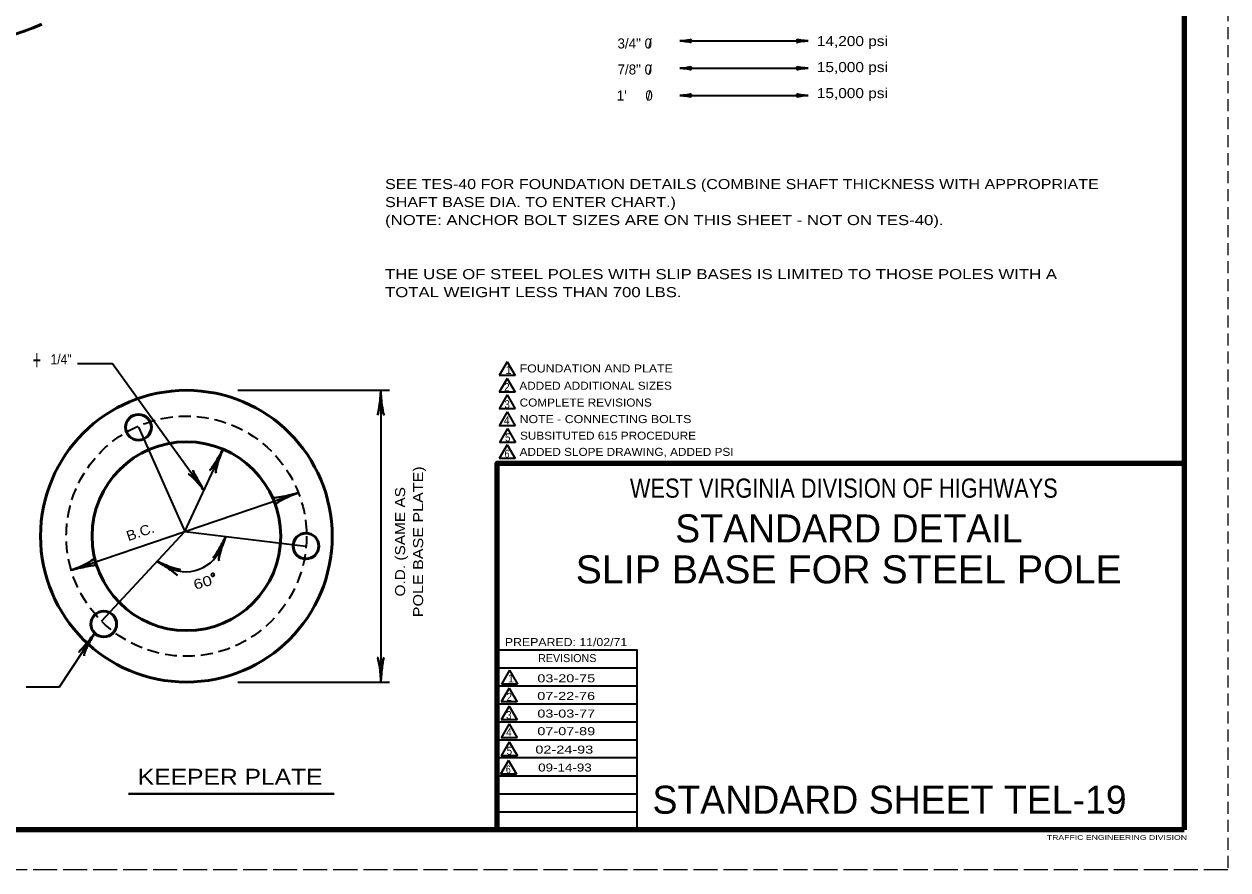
# Model space of a CAD drawing. Extents: x -2 to 678, y 0 to 440.
# Drawn here: x 377.6 to 678.4, y -0.1 to 211.2 of the extents above; entities that cross this region are included whole.
import ezdxf
from ezdxf.enums import TextEntityAlignment as Align

# ---------------------------------------------------------------- set-up
doc = ezdxf.new("R2010")
doc.units = 0
doc.linetypes.add('LONG_DASHED', pattern=[7.5, 6, -1.5])
doc.linetypes.add('MEDIUM_DASHED', pattern=[4.5, 3, -1.5])
doc.layers.add('1', color=7, linetype='Continuous', lineweight=53)
doc.layers.add('61', color=7, linetype='Continuous', lineweight=35)

msp = doc.modelspace()

# ---------------------------------------------------------------- linework, layer by layer
at = {"layer": '1', "linetype": 'MEDIUM_DASHED', "lineweight": 13}
msp.add_line((678.423, 439.973), (678.403, -0.047), dxfattribs=at)
at = {"layer": '1', "lineweight": 35}
for p, q in [((541.511, 207.033), (573.511, 207.033)), ((541.511, 200.213), (573.511, 200.213)), ((541.511, 193.392), (573.511, 193.392)), ((498.341, 126.882), (496.341, 123.418)), ((498.341, 126.882), (500.341, 123.418)), ((500.341, 123.418), (496.341, 123.418)), ((498.326, 122.716), (496.326, 119.252)), ((498.326, 122.716), (500.326, 119.252)), ((431.057, 119.74), (468.914, 119.74)), ((466.77, 119.74), (466.77, 46.858)), ((500.326, 119.252), (496.326, 119.252)), ((498.361, 118.585), (496.361, 115.121)), ((498.361, 118.585), (500.361, 115.121)), ((500.361, 115.121), (496.361, 115.121)), ((498.361, 114.341), (496.361, 110.877)), ((498.361, 114.341), (500.361, 110.877)), ((500.361, 110.877), (496.361, 110.877)), ((498.444, 110.203), (496.444, 106.739)), ((498.444, 110.203), (500.444, 106.739)), ((498.356, 106.151), (496.356, 102.686)), ((500.444, 106.739), (496.444, 106.739)), ((498.356, 106.151), (500.356, 102.686)), ((417.796, 84.471), (427.351, 105.028)), ((500.356, 102.686), (496.356, 102.686)), ((389.417, 74.79), (446.175, 94.153)), ((396.975, 62.078), (417.796, 84.471)), ((530.803, 50.373), (495.823, 50.373)), ((498.882, 49.832), (496.882, 46.368)), ((498.882, 49.832), (500.882, 46.368)), ((431.057, 46.858), (468.914, 46.858)), ((530.803, 45.873), (495.823, 45.873)), ((498.827, 45.377), (496.827, 41.913)), ((500.882, 46.368), (496.882, 46.368)), ((498.827, 45.377), (500.827, 41.913)), ((530.803, 41.373), (495.823, 41.373)), ((500.827, 41.913), (496.827, 41.913)), ((498.839, 40.879), (496.839, 37.415)), ((498.839, 40.879), (500.839, 37.415)), ((530.803, 36.853), (495.823, 36.853)), ((500.839, 37.415), (496.839, 37.415)), ((498.847, 36.401), (496.847, 32.937)), ((498.847, 36.401), (500.847, 32.937)), ((530.803, 32.373), (495.823, 32.373)), ((500.847, 32.937), (496.847, 32.937)), ((498.88, 31.915), (496.88, 28.45)), ((498.88, 31.915), (500.88, 28.45)), ((530.803, 27.893), (495.823, 27.893)), ((498.686, 27.303), (496.686, 23.839)), ((500.88, 28.45), (496.88, 28.45)), ((498.686, 27.303), (500.686, 23.839)), ((530.803, 23.393), (495.823, 23.393)), ((500.686, 23.839), (496.686, 23.839)), ((530.803, 18.893), (495.823, 18.893)), ((530.803, 14.373), (495.823, 14.373))]:
    msp.add_line(p, q, dxfattribs=at)
at = {"layer": '1', "lineweight": 40}
msp.add_line((403.734, 18.941), (455.095, 18.941), dxfattribs=at)
at = {"layer": '1', "lineweight": 35}
for points in [[(422.573, 94.75), (399.746, 126.363), (390.973, 126.363)], [(406.218, 110.509), (417.796, 84.471), (448.062, 80.845)], [(395.279, 59.083), (386.426, 45.554), (378.139, 45.554)], [(530.803, 9.893), (530.803, 54.853), (495.823, 54.853)]]:
    msp.add_lwpolyline(points, dxfattribs=at)
at = {"layer": '1', "lineweight": 158}
msp.add_lwpolyline([(495.803, 9.933), (495.803, 101.513), (667.463, 101.513)], dxfattribs=at)
at = {"layer": '1'}
for centre, radius in [((418.196, 83.299), 36.441), ((406.218, 110.509), 3.215), ((418.196, 83.299), 23.579), ((448.062, 80.845), 3.215), ((397.552, 61.357), 3.215)]:
    msp.add_circle(centre, radius, dxfattribs=at)
at = {"layer": '1', "linetype": 'MEDIUM_DASHED', "lineweight": 35}
msp.add_circle((418.196, 83.299), 30.01, dxfattribs=at)
at = {"layer": '1', "lineweight": 35}
msp.add_circle((424.796, 73.648), 0.394, dxfattribs=at)
at = {"layer": '1'}
msp.add_arc((363.469, 250.283), 43.26, 245.44681, 295.48154, dxfattribs=at)
at = {"layer": '1', "lineweight": 35}
msp.add_arc((418.077, 83.89), 9.464, 237.85816, 343.17714, dxfattribs=at)
at = {"layer": '1', "lineweight": 40}
for centre, major_axis, ratio, start_param, end_param in [((542.631, 206.821), (1.756, -0.176), 0.07063, 6.2823074, 8.5597026), ((542.631, 206.821), (1.756, -0.176), 0.07063, 6.2823074, 8.5597026), ((542.602, 207.309), (-1.786, -0.156), 0.122415, 0.8963533, 3.1415927), ((542.602, 207.309), (-1.786, -0.156), 0.122415, 0.8963533, 3.1415927), ((572.42, 206.757), (1.786, 0.156), 0.122415, 0.8963533, 3.1415927), ((572.42, 206.757), (1.786, 0.156), 0.122415, 0.8963533, 3.1415927), ((572.39, 207.245), (-1.756, 0.176), 0.07063, 6.2823074, 8.5597026), ((572.39, 207.245), (-1.756, 0.176), 0.07063, 6.2823074, 8.5597026), ((542.631, 200.001), (1.756, -0.176), 0.07063, 6.2823074, 8.5597026), ((542.631, 200.001), (1.756, -0.176), 0.07063, 6.2823074, 8.5597026), ((542.602, 200.489), (-1.786, -0.156), 0.122415, 0.8963533, 3.1415927), ((542.602, 200.489), (-1.786, -0.156), 0.122415, 0.8963533, 3.1415927), ((572.42, 199.936), (1.786, 0.156), 0.122415, 0.8963533, 3.1415927), ((572.42, 199.936), (1.786, 0.156), 0.122415, 0.8963533, 3.1415927), ((572.39, 200.424), (-1.756, 0.176), 0.07063, 6.2823074, 8.5597026), ((572.39, 200.424), (-1.756, 0.176), 0.07063, 6.2823074, 8.5597026), ((542.631, 193.181), (1.756, -0.176), 0.07063, 6.2823074, 8.5597026), ((542.602, 193.669), (-1.786, -0.156), 0.122415, 0.8963533, 3.1415927), ((572.42, 193.116), (1.786, 0.156), 0.122415, 0.8963533, 3.1415927), ((572.42, 193.116), (1.786, 0.156), 0.122415, 0.8963533, 3.1415927), ((572.39, 193.604), (-1.756, 0.176), 0.07063, 6.2823074, 8.5597026), ((572.39, 193.604), (-1.756, 0.176), 0.07063, 6.2823074, 8.5597026), ((466.316, 117.338), (0.377, 3.765), 0.07063, 3.1407148, 5.41811), ((466.316, 117.338), (0.377, 3.765), 0.07063, 3.1407148, 5.41811), ((467.362, 117.401), (-0.335, 3.828), 0.122415, 0.8963533, 3.1415927), ((467.362, 117.401), (-0.335, 3.828), 0.122415, 0.8963533, 3.1415927), ((425.927, 103.041), (1.928, 3.256), 0.07063, 3.1407148, 5.41811), ((426.902, 102.657), (1.31, 3.612), 0.122415, 0.8963533, 3.1415927), ((421.632, 96.785), (1.726, -2.975), 0.07063, 3.1407148, 5.41811), ((420.894, 96.182), (2.284, -2.643), 0.122415, 0.8963533, 3.1415927), ((443.755, 93.806), (3.685, 0.859), 0.07063, 3.1407148, 5.41811), ((443.755, 93.806), (3.685, 0.859), 0.07063, 3.1407148, 5.41811), ((444.152, 92.837), (3.515, 1.553), 0.122415, 0.8963533, 3.1415927), ((444.152, 92.837), (3.515, 1.553), 0.122415, 0.8963533, 3.1415927), ((426.671, 81.169), (1.898, 3.273), 0.07063, 3.1407148, 5.41811), ((427.65, 80.794), (1.277, 3.624), 0.122415, 0.8963533, 3.1415927), ((391.439, 76.106), (-3.515, -1.553), 0.122415, 0.8963533, 3.1415927), ((391.439, 76.106), (-3.515, -1.553), 0.122415, 0.8963533, 3.1415927), ((391.837, 75.136), (-3.685, -0.859), 0.07063, 3.1407148, 5.41811), ((391.837, 75.136), (-3.685, -0.859), 0.07063, 3.1407148, 5.41811), ((412.762, 75.552), (-3.168, 2.07), 0.07063, 3.1407148, 5.41811), ((413.188, 76.51), (-3.551, 1.467), 0.122415, 0.8963533, 3.1415927), ((393.584, 57.322), (2.377, 2.944), 0.07063, 3.1407148, 5.41811), ((394.493, 56.801), (1.816, 3.386), 0.122415, 0.8963533, 3.1415927), ((466.178, 49.197), (0.335, -3.828), 0.122415, 0.8963533, 3.1415927), ((467.224, 49.259), (-0.377, -3.765), 0.07063, 3.1407148, 5.41811)]:
    msp.add_ellipse(centre, major_axis=major_axis, ratio=ratio, start_param=start_param, end_param=end_param, dxfattribs=at)
at = {"layer": '61', "lineweight": 158}
for p, q in [((667.443, 429.973), (667.463, 9.933)), ((667.463, 9.933), (28.403, 9.953))]:
    msp.add_line(p, q, dxfattribs=at)
at = {"layer": '61', "linetype": 'LONG_DASHED', "lineweight": 13}
msp.add_line((678.403, -0.047), (-1.657, -0.067), dxfattribs=at)

# ---------------------------------------------------------------- texts
at = {"layer": '1'}
for s, height, p in [('3/4" 0', 2.5, (530.222, 205.139)), ('7/8" 0', 2.5, (530.222, 198.639)), ("1'     0", 2.5, (530.222, 192.139)), ('STANDARD DETAIL', 6.993, (583.72, 81.753))]:
    msp.add_text(s, height=height, dxfattribs=at).set_placement(p, align=Align.CENTER)
for s, height, p in [('/', 2.5, (533.541, 205.152)), ('/', 2.5, (533.592, 198.576)), ('/', 2.5, (533.287, 192.152)), ('1', 2, (497.947, 123.823)), ('REVISIONS', 1.998, (506.083, 51.853)), ('1', 2, (498.53, 46.77)), ('STANDARD SHEET TEL-19', 6.993, (534.643, 13.973))]:
    msp.add_text(s, height=height, dxfattribs=at).set_placement(p)
for s, height, width, p in [('14,200 psi', 2.5, 1.15, (584.594, 205.741)), ('15,000 psi', 2.5, 1.15, (584.594, 199.241)), ('15,000 psi', 2.5, 1.15, (584.594, 192.741)), ('WEST VIRGINIA DIVISION OF HIGHWAYS', 4.795, 0.85, (582.452, 92.913)), ('SLIP BASE FOR STEEL POLE', 6.993, 1.05, (583.674, 71.516)), ('03-20-75', 2, 1.35, (513.103, 46.793)), ('07-22-76', 2, 1.35, (513.083, 42.393)), ('03-03-77', 2, 1.35, (513.103, 37.993)), ('07-07-89', 2, 1.35, (513.103, 33.593)), ('02-24-93', 2, 1.35, (512.613, 28.993)), ('KEEPER PLATE', 4, 1.15, (429.129, 21.194)), ('09-14-93', 2, 1.25, (512.773, 24.513))]:
    msp.add_text(s, height=height, dxfattribs=dict(at, width=width)).set_placement(p, align=Align.CENTER)
for s, height, width, p in [('SEE TES-40 FOR FOUNDATION DETAILS (COMBINE SHAFT THICKNESS WITH APPROPRIATE', 2.5, 1.2, (467.833, 170.013)), ('SHAFT BASE DIA. TO ENTER CHART.)', 2.5, 1.2, (467.833, 165.513)), ('(NOTE: ANCHOR BOLT SIZES ARE ON THIS SHEET - NOT ON TES-40).', 2.5, 1.25, (467.833, 161.013)), ('THE USE OF STEEL POLES WITH SLIP BASES IS LIMITED TO THOSE POLES WITH A', 2.5, 1.25, (467.833, 147.513)), ('TOTAL WEIGHT LESS THAN 700 LBS.', 2.5, 1.25, (467.833, 143.013)), ('+', 5, 0.55, (379.744, 124.846)), ('1/4"', 2.5, 0.9, (384.252, 126.227)), ('FOUNDATION AND PLATE', 2, 1.15, (501.457, 124.205)), ('2', 2, 0.9, (497.599, 119.547)), ('ADDED ADDITIONAL SIZES', 2, 1.1, (501.388, 119.894)), ('COMPLETE REVISIONS', 2, 1.1, (501.457, 115.688)), ('3', 2, 0.9, (497.669, 115.271)), ('4', 2, 0.95, (497.53, 111.238)), ('NOTE - CONNECTING BOLTS', 2, 1.15, (501.457, 111.551)), ('5', 2, 0.9, (497.795, 106.963)), ('SUBSITUTED 615 PROCEDURE', 2, 1.1, (501.54, 107.412)), ('ADDED SLOPE DRAWING, ADDED PSI', 2, 1.1, (501.452, 103.36)), ('6', 2, 0.8, (497.707, 102.91)), ('PREPARED: 11/02/71', 1.998, 1.15, (497.763, 55.853)), ('2', 2, 0.9, (498.188, 42.148)), ('3', 2, 0.9, (498.102, 37.613)), ('4', 2, 0.95, (498.06, 33.334)), ('5', 2, 0.9, (498.225, 28.682)), ('6', 2, 0.8, (498.037, 24.062)), ('TRAFFIC ENGINEERING DIVISION', 1.2, 1.35, (633.183, 7.433))]:
    msp.add_text(s, height=height, dxfattribs=dict(at, width=width)).set_placement(p)
for s, width, p in [('POLE BASE PLATE)', 1.2, (477.341, 81.907)), ('O.D. (SAME AS', 1.15, (472.841, 81.907))]:
    msp.add_text(s, height=2.5, rotation=90, dxfattribs=dict(at, width=width)).set_placement(p, align=Align.CENTER)
for s, rotation, width, p in [('B.C.', 18.836, 1.1, (403.685, 82.039)), ('60', 16.257, 1.25, (420.382, 69.896))]:
    msp.add_text(s, height=2.5, rotation=rotation, dxfattribs=dict(at, width=width)).set_placement(p)

doc.saveas('drawing.dxf')
